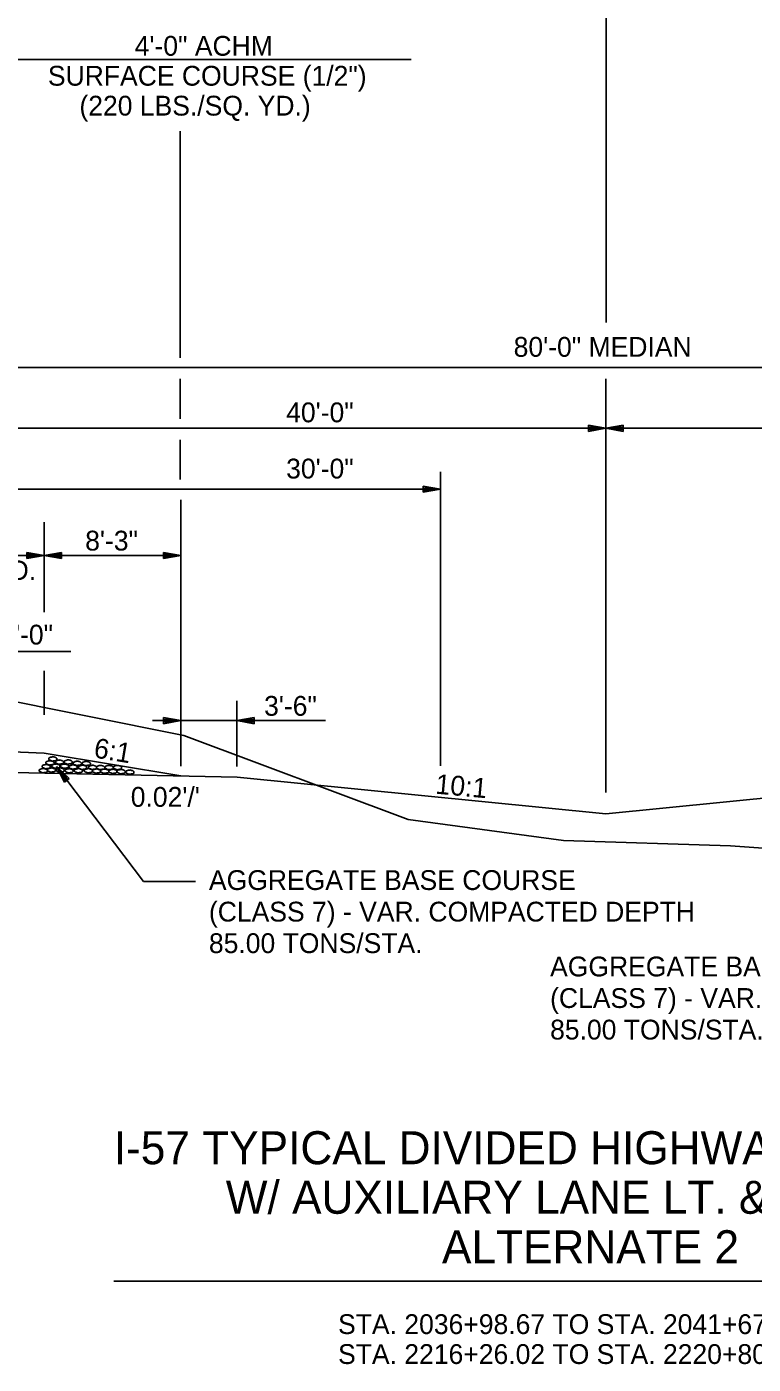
# Model space of a CAD drawing. Extents: x 1734743 to 1735935, y 759845 to 763831.
# Drawn here: x 1735722.6 to 1735766.6, y 760542.6 to 760623.7 of the extents above; entities that cross this region are included whole.
import ezdxf

# ---------------------------------------------------------------- set-up
doc = ezdxf.new("R2010")
doc.units = 0
for name, color, linetype in [('1', 7, 'Continuous'), ('19', 7, 'Continuous'), ('Level 1', 7, 'Continuous')]:
    doc.layers.add(name, color=color, linetype=linetype)

# ---------------------------------------------------------------- blocks, each defined once
blk = doc.blocks.new('ROCKS')
at = {"layer": '1'}
blk.add_spline([(0.013, 0.06), (0.053, 0.053), (0.107, 0.033), (0.133, 0.013), (0.133, -0.007), (0.12, -0.033), (0.107, -0.04), (0.073, -0.053), (0.033, -0.067), (0.013, -0.067), (-0.02, -0.06), (-0.06, -0.053), (-0.087, -0.047), (-0.113, -0.02), (-0.113, -0.007), (-0.107, 0.02), (-0.087, 0.033), (-0.067, 0.047), (-0.033, 0.053), (-0.02, 0.06), (0.013, 0.06)], degree=3, dxfattribs=at)

msp = doc.modelspace()

# ---------------------------------------------------------------- linework, layer by layer
at = {"layer": '19'}
for p, q in [((1735757.721, 760605.749), (1735757.721, 760638.822)), ((1735721.698, 760621.695), (1735745.908, 760621.695)), ((1735731.94, 760603.611), (1735731.94, 760617.356)), ((1735717.701, 760603.031), (1735797.701, 760603.031)), ((1735731.94, 760599.924), (1735731.94, 760602.333)), ((1735757.701, 760577.281), (1735757.701, 760602.333)), ((1735717.701, 760599.345), (1735757.701, 760599.345)), ((1735756.651, 760599.528), (1735756.651, 760599.161)), ((1735757.701, 760599.345), (1735756.651, 760599.528)), ((1735757.421, 760599.371), (1735756.651, 760599.432)), ((1735756.651, 760599.161), (1735757.701, 760599.345)), ((1735756.651, 760599.248), (1735757.421, 760599.318)), ((1735758.751, 760599.528), (1735757.701, 760599.345)), ((1735757.701, 760599.345), (1735758.751, 760599.161)), ((1735757.701, 760599.345), (1735797.701, 760599.345)), ((1735758.751, 760599.432), (1735757.981, 760599.371)), ((1735757.981, 760599.318), (1735758.751, 760599.248)), ((1735758.751, 760599.161), (1735758.751, 760599.528)), ((1735731.94, 760596.238), (1735731.94, 760598.646)), ((1735747.701, 760578.902), (1735747.701, 760596.704)), ((1735717.701, 760595.658), (1735747.701, 760595.658)), ((1735746.651, 760595.842), (1735746.651, 760595.474)), ((1735747.701, 760595.658), (1735746.651, 760595.842)), ((1735747.421, 760595.684), (1735746.651, 760595.745)), ((1735746.651, 760595.474), (1735747.701, 760595.658)), ((1735746.651, 760595.562), (1735747.421, 760595.632)), ((1735731.976, 760580.301), (1735731.976, 760595.02)), ((1735723.701, 760588.199), (1735723.701, 760593.654)), ((1735717.701, 760591.641), (1735723.701, 760591.641)), ((1735722.651, 760591.825), (1735722.651, 760591.457)), ((1735723.701, 760591.641), (1735722.651, 760591.825)), ((1735723.421, 760591.667), (1735722.651, 760591.729)), ((1735722.651, 760591.457), (1735723.701, 760591.641)), ((1735722.651, 760591.545), (1735723.421, 760591.615)), ((1735724.751, 760591.825), (1735723.701, 760591.641)), ((1735723.701, 760591.641), (1735724.751, 760591.457)), ((1735723.701, 760591.641), (1735731.976, 760591.641)), ((1735724.751, 760591.729), (1735723.981, 760591.667)), ((1735723.981, 760591.615), (1735724.751, 760591.545)), ((1735724.751, 760591.457), (1735724.751, 760591.825)), ((1735730.926, 760591.825), (1735730.926, 760591.457)), ((1735731.976, 760591.641), (1735730.926, 760591.825)), ((1735731.696, 760591.667), (1735730.926, 760591.729)), ((1735730.926, 760591.457), (1735731.976, 760591.641)), ((1735730.926, 760591.545), (1735731.696, 760591.615)), ((1735719.7, 760585.829), (1735725.31, 760585.826)), ((1735723.701, 760581.987), (1735723.701, 760584.659)), ((1735735.374, 760578.848), (1735735.374, 760582.838)), ((1735730.263, 760581.631), (1735740.724, 760581.631)), ((1735730.926, 760581.815), (1735730.926, 760581.448)), ((1735731.976, 760581.631), (1735730.926, 760581.815)), ((1735731.696, 760581.657), (1735730.926, 760581.719)), ((1735730.926, 760581.448), (1735731.976, 760581.631)), ((1735730.926, 760581.535), (1735731.696, 760581.605)), ((1735736.424, 760581.815), (1735735.374, 760581.631)), ((1735735.374, 760581.631), (1735736.424, 760581.447)), ((1735736.424, 760581.719), (1735735.654, 760581.657)), ((1735735.654, 760581.605), (1735736.424, 760581.535)), ((1735736.424, 760581.447), (1735736.424, 760581.815)), ((1735717.701, 760579.903), (1735723.701, 760579.663)), ((1735731.976, 760578.871), (1735731.976, 760580.301)), ((1735723.701, 760579.663), (1735731.976, 760578.284)), ((1735719.689, 760578.529), (1735735.386, 760578.216)), ((1735724.44, 760578.858), (1735729.722, 760571.888)), ((1735724.927, 760577.913), (1735724.44, 760578.858)), ((1735724.44, 760578.858), (1735725.219, 760578.131)), ((1735724.995, 760577.966), (1735724.585, 760578.619)), ((1735724.624, 760578.649), (1735725.142, 760578.079)), ((1735725.219, 760578.131), (1735724.927, 760577.913)), ((1735735.386, 760578.216), (1735757.701, 760575.984)), ((1735735.386, 760578.216), (1735757.701, 760575.984)), ((1735780.015, 760578.216), (1735757.701, 760575.984)), ((1735780.018, 760578.216), (1735757.701, 760575.984)), ((1735729.722, 760571.888), (1735732.858, 760571.888)), ((1735727.916, 760547.667), (1735787.554, 760547.667))]:
    msp.add_line(p, q, dxfattribs=at)
for points in [[(1735713.47, 760583.454), (1735720.263, 760583.114), (1735732.151, 760580.734), (1735745.738, 760575.634), (1735755.142, 760574.378)], [(1735789.496, 760572.309), (1735765.245, 760574.046), (1735755.142, 760574.378)]]:
    msp.add_lwpolyline(points, dxfattribs=at)

# ---------------------------------------------------------------- block references
at = {"layer": 'Level 1', "xscale": 2.011654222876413, "yscale": -2.011654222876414, "rotation": 178.00441377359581}
for p in [(1735723.845, 760578.853), (1735724.077, 760579.079), (1735724.251, 760579.318), (1735724.428, 760578.881), (1735724.652, 760579.123), (1735724.954, 760578.878), (1735725.174, 760579.132), (1735725.468, 760578.829), (1735725.727, 760579.052), (1735726.042, 760578.808), (1735726.274, 760579.042), (1735726.65, 760578.806), (1735727.142, 760578.798), (1735727.653, 760578.797), (1735728.164, 760578.795), (1735723.668, 760578.608), (1735724.164, 760578.644), (1735724.696, 760578.642), (1735725.229, 760578.601), (1735725.789, 760578.604), (1735726.397, 760578.602), (1735726.888, 760578.584), (1735727.384, 760578.575), (1735727.88, 760578.563), (1735728.38, 760578.548), (1735728.908, 760578.517)]:
    msp.add_blockref('ROCKS', p, dxfattribs=at)

# ---------------------------------------------------------------- texts
at = {"layer": '19'}
for s, height, p in [('4\'-0" ACHM ', 1.2, (1735729.181, 760621.917)), ('SURFACE COURSE (1/2")', 1.2, (1735723.927, 760620.104)), ('(220 LBS./SQ. YD.)', 1.2, (1735725.836, 760618.292)), ('80\'-0" MEDIAN', 1.2, (1735752.122, 760603.678)), ('40\'-0"', 1.2, (1735738.35, 760599.709)), ('30\'-0"', 1.2, (1735738.35, 760596.305)), ('8\'-3"', 1.2, (1735726.185, 760591.938)), ('SHLD.', 1.2, (1735718.49, 760590.145)), ('2\'-0"', 1.2, (1735721.044, 760586.244)), ('3\'-6"', 1.2, (1735737.014, 760581.928)), ("0.02'/'", 1.2, (1735728.944, 760576.413)), ('I-57 TYPICAL DIVIDED HIGHWAY SECTION', 2, (1735727.916, 760554.756)), ('W/ AUXILIARY LANE LT. & RT.', 2, (1735734.696, 760551.756)), ('ALTERNATE 2', 2, (1735747.782, 760548.756)), ('STA. 2036+98.67 TO STA. 2041+67.66', 1.2, (1735741.492, 760544.467)), ('STA. 2216+26.02 TO STA. 2220+80.51', 1.2, (1735741.492, 760542.654))]:
    msp.add_text(s, height=height, dxfattribs=at).set_placement(p)
for s, rotation, p in [('6:1', 350.54888, (1735726.655, 760579.411)), ('10:1', 354.84221, (1735747.354, 760577.211)), ('AGGREGATE BASE COURSE', 360, (1735733.675, 760571.372)), ('(CLASS 7) - VAR. COMPACTED DEPTH', 360, (1735733.675, 760569.46)), ('85.00 TONS/STA.', 360, (1735733.675, 760567.549)), ('AGGREGATE BASE COURSE', 360, (1735754.328, 760566.137)), ('(CLASS 7) - VAR. COMPACTED DEPTH', 360, (1735754.328, 760564.225)), ('85.00 TONS/STA.', 360, (1735754.328, 760562.313))]:
    msp.add_text(s, height=1.2, rotation=rotation, dxfattribs=at).set_placement(p)

doc.saveas('drawing.dxf')
